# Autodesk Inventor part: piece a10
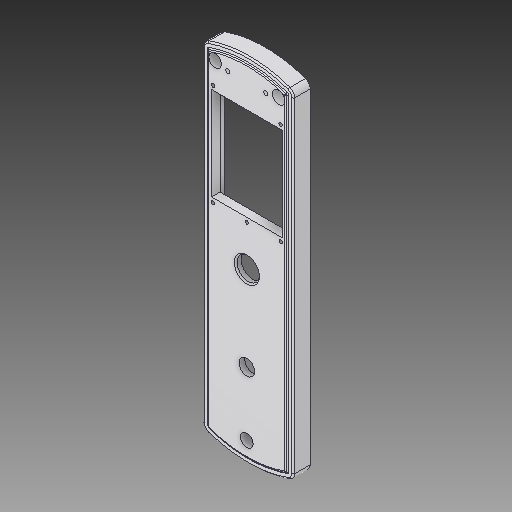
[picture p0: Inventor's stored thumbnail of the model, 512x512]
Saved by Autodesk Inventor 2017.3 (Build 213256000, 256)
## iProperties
Created: 2002-03
Part Number: piece a10
Material: solidworks materials|Alliage 7079|22
Document SubType Name: Modeling
Designer: ficho
Density: 2.7 g/cm^3
Appearance: 227,227,2331
Author: ficho
Sending System: SolidWorks 2009
Last Author: christophe
Last Saved: 2011-02-10
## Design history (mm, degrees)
feature "Nervure5"
node "Solide1"
